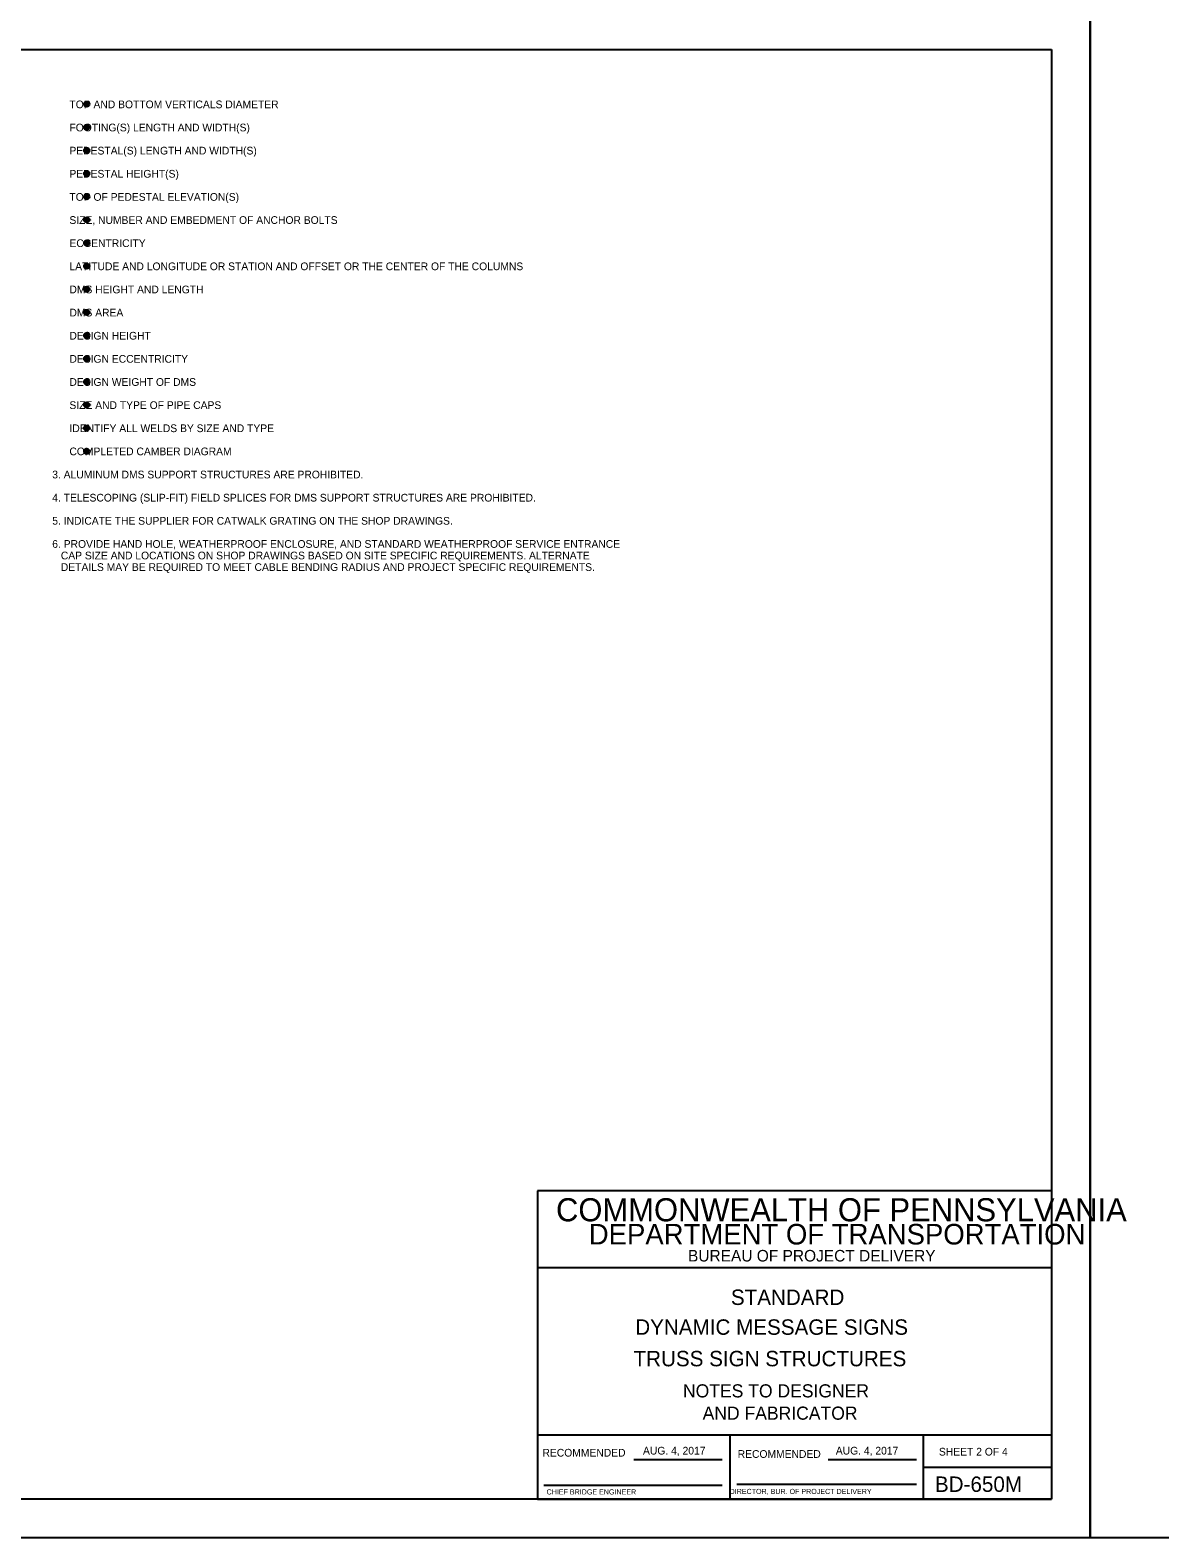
# Model space of a CAD drawing. Extents: x 3831399 to 3833095, y 499014 to 500202.
# Drawn here: x 3831828 to 3832267, y 499014 to 499601 of the extents above; entities that cross this region are included whole.
import ezdxf

# ---------------------------------------------------------------- set-up
doc = ezdxf.new("R2010")
doc.units = 0
for name, color, linetype in [('10', 7, 'Continuous'), ('2', 7, 'Continuous'), ('DIM TXT', 7, 'Continuous'), ('PLT-BNDY', 7, 'Continuous'), ('Pr_dimension_ln', 7, 'Continuous')]:
    doc.layers.add(name, color=color, linetype=linetype)

msp = doc.modelspace()

# ---------------------------------------------------------------- linework, layer by layer
at = {"layer": '2'}
for p, q in [((3831439.16, 499593.03), (3832225.16, 499593.03)), ((3832225.16, 499593.03), (3832225.16, 499029.03)), ((3832225.16, 499149.03), (3832025.16, 499149.03)), ((3832025.16, 499149.03), (3832025.16, 499029.03)), ((3832225.16, 499119.03), (3832025.16, 499119.03)), ((3832225.16, 499054.03), (3832025.16, 499054.03)), ((3832100.16, 499029.03), (3832100.16, 499054.03)), ((3832175.16, 499054.03), (3832175.16, 499029.03)), ((3832062.62, 499044.53), (3832097.03, 499044.53)), ((3832138.24, 499044.53), (3832172.65, 499044.53)), ((3832175.16, 499041.53), (3832225.16, 499041.53)), ((3832027.66, 499034.53), (3832097.03, 499034.53)), ((3832102.79, 499034.9), (3832172.65, 499034.9)), ((3832225.16, 499029.03), (3831439.16, 499029.03)), ((3832025.16, 499029.03), (3832225.16, 499029.03))]:
    msp.add_line(p, q, dxfattribs=at)
at = {"layer": 'DIM TXT'}
for centre, radius in [((3831849.87, 499571.73), 1.04), ((3831849.87, 499571.73), 0.783), ((3831849.87, 499571.73), 0.522), ((3831849.87, 499571.73), 0.261), ((3831849.87, 499571.73), 0.00000209), ((3831849.87, 499562.73), 1.04), ((3831849.87, 499562.73), 0.783), ((3831849.87, 499562.73), 0.522), ((3831849.87, 499562.73), 0.261), ((3831849.87, 499562.73), 0.00000209), ((3831849.87, 499553.73), 1.04), ((3831849.87, 499553.73), 0.783), ((3831849.87, 499553.73), 0.522), ((3831849.87, 499553.73), 0.261), ((3831849.87, 499553.73), 0.00000209), ((3831849.87, 499544.73), 1.04), ((3831849.87, 499544.73), 0.783), ((3831849.87, 499544.73), 0.522), ((3831849.87, 499544.73), 0.261), ((3831849.87, 499544.73), 0.00000209), ((3831849.87, 499535.73), 1.04), ((3831849.87, 499535.73), 0.783), ((3831849.87, 499535.73), 0.522), ((3831849.87, 499535.73), 0.261), ((3831849.87, 499535.73), 0.00000209), ((3831849.87, 499526.73), 1.04), ((3831849.87, 499526.73), 0.783), ((3831849.87, 499526.73), 0.522), ((3831849.87, 499526.73), 0.261), ((3831849.87, 499526.73), 0.00000209), ((3831849.87, 499517.73), 1.04), ((3831849.87, 499517.73), 0.783), ((3831849.87, 499517.73), 0.522), ((3831849.87, 499517.73), 0.261), ((3831849.87, 499517.73), 0.00000209), ((3831849.87, 499508.73), 1.04), ((3831849.87, 499508.73), 0.783), ((3831849.87, 499508.73), 0.522), ((3831849.87, 499508.73), 0.261), ((3831849.87, 499508.73), 0.00000209), ((3831849.87, 499499.73), 1.04), ((3831849.87, 499499.73), 0.783), ((3831849.87, 499499.73), 0.522), ((3831849.87, 499499.73), 0.261), ((3831849.87, 499499.73), 0.00000209), ((3831849.87, 499490.73), 1.04), ((3831849.87, 499490.73), 0.783), ((3831849.87, 499490.73), 0.522), ((3831849.87, 499490.73), 0.261), ((3831849.87, 499490.73), 0.00000209), ((3831849.87, 499481.73), 1.04), ((3831849.87, 499481.73), 0.783), ((3831849.87, 499481.73), 0.522), ((3831849.87, 499481.73), 0.261), ((3831849.87, 499481.73), 0.00000209), ((3831849.87, 499472.73), 1.04), ((3831849.87, 499472.73), 0.783), ((3831849.87, 499472.73), 0.522), ((3831849.87, 499472.73), 0.261), ((3831849.87, 499472.73), 0.00000209), ((3831849.87, 499463.73), 1.04), ((3831849.87, 499463.73), 0.783), ((3831849.87, 499463.73), 0.522), ((3831849.87, 499463.73), 0.261), ((3831849.87, 499463.73), 0.00000209), ((3831849.87, 499454.73), 1.04), ((3831849.87, 499454.73), 0.783), ((3831849.87, 499454.73), 0.522), ((3831849.87, 499454.73), 0.261), ((3831849.87, 499454.73), 0.00000209), ((3831849.87, 499445.73), 1.04), ((3831849.87, 499445.73), 0.783), ((3831849.87, 499445.73), 0.522), ((3831849.87, 499445.73), 0.261), ((3831849.87, 499445.73), 0.00000209), ((3831849.87, 499436.73), 1.04), ((3831849.87, 499436.73), 0.783), ((3831849.87, 499436.73), 0.522), ((3831849.87, 499436.73), 0.261), ((3831849.87, 499436.73), 0.00000209)]:
    msp.add_circle(centre, radius, dxfattribs=at)
at = {"layer": 'PLT-BNDY'}
for points in [[(3831399.16, 499608.03), (3832240.16, 499608.03), (3832240.16, 499014.03), (3831399.16, 499014.03)], [(3832240.16, 499608.03), (3833081.16, 499608.03), (3833081.16, 499014.03), (3832240.16, 499014.03)]]:
    msp.add_lwpolyline(points, close=True, dxfattribs=at)

# ---------------------------------------------------------------- texts
at = {"layer": '10'}
for s, height, p in [('STANDARD ', 6, (3832100.43, 499104.62)), ('DYNAMIC MESSAGE SIGNS', 6, (3832063.23, 499093.02)), ('TRUSS SIGN STRUCTURES', 6, (3832062.56, 499080.76)), ('NOTES TO DESIGNER', 5.1, (3832081.79, 499068.66)), ('AND FABRICATOR', 5.1, (3832089.44, 499059.99))]:
    msp.add_text(s, height=height, dxfattribs=at).set_placement(p)
at = {"layer": '2'}
for s, height, p in [('COMMONWEALTH OF PENNSYLVANIA', 9, (3832032.41, 499137.15)), ('DEPARTMENT OF TRANSPORTATION', 8.0002, (3832045.16, 499128.15)), ('BUREAU OF PROJECT DELIVERY', 4.5, (3832083.75, 499121.53)), ('AUG. 4, 2017', 3, (3832066.24, 499046.44)), ('AUG. 4, 2017', 3, (3832141.24, 499046.44)), ('SHEET 2 OF 4', 3, (3832181.36, 499046.04)), ('BD-650M', 6, (3832179.79, 499031.9)), ('CHIEF BRIDGE ENGINEER', 2.0002, (3832028.75, 499030.9)), ('   DIRECTOR, BUR. OF PROJECT DELIVERY', 2.0002, (3832097.63, 499031.08))]:
    msp.add_text(s, height=height, dxfattribs=at).set_placement(p)
for p in [(3832027.14, 499045.64), (3832103.07, 499045.15)]:
    msp.add_text('RECOMMENDED', height=3, rotation=360, dxfattribs=at).set_placement(p)
at = {"layer": 'Pr_dimension_ln'}
for s, p in [('       TOP AND BOTTOM VERTICALS DIAMETER', (3831835.34, 499570.15)), ('       FOOTING(S) LENGTH AND WIDTH(S)', (3831835.34, 499561.15)), ('       PEDESTAL(S) LENGTH AND WIDTH(S)', (3831835.34, 499552.16)), ('       PEDESTAL HEIGHT(S)', (3831835.34, 499543.16)), ('       TOP OF PEDESTAL ELEVATION(S)', (3831835.34, 499534.16)), ('       SIZE, NUMBER AND EMBEDMENT OF ANCHOR BOLTS', (3831835.34, 499525.16)), ('       ECCENTRICITY', (3831835.34, 499516.16)), ('       LATITUDE AND LONGITUDE OR STATION AND OFFSET OR THE CENTER OF THE COLUMNS', (3831835.34, 499507.16)), ('       DMS HEIGHT AND LENGTH', (3831835.34, 499498.16)), ('       DMS AREA', (3831835.34, 499489.16)), ('       DESIGN HEIGHT', (3831835.34, 499480.16)), ('       DESIGN ECCENTRICITY', (3831835.34, 499471.16)), ('       DESIGN WEIGHT OF DMS', (3831835.34, 499462.16)), ('       SIZE AND TYPE OF PIPE CAPS', (3831835.34, 499453.16)), ('       IDENTIFY ALL WELDS BY SIZE AND TYPE', (3831835.34, 499444.16)), ('       COMPLETED CAMBER DIAGRAM', (3831835.34, 499435.16)), (' 3. ALUMINUM DMS SUPPORT STRUCTURES ARE PROHIBITED.', (3831835.34, 499426.16)), (' 4. TELESCOPING (SLIP-FIT) FIELD SPLICES FOR DMS SUPPORT STRUCTURES ARE PROHIBITED.', (3831835.34, 499417.16)), (' 5. INDICATE THE SUPPLIER FOR CATWALK GRATING ON THE SHOP DRAWINGS.', (3831835.34, 499408.16)), (' 6. PROVIDE HAND HOLE, WEATHERPROOF ENCLOSURE, AND STANDARD WEATHERPROOF SERVICE ENTRANCE ', (3831835.34, 499399.16)), ('    CAP SIZE AND LOCATIONS ON SHOP DRAWINGS BASED ON SITE SPECIFIC REQUIREMENTS. ALTERNATE', (3831835.34, 499394.66)), ('    DETAILS MAY BE REQUIRED TO MEET CABLE BENDING RADIUS AND PROJECT SPECIFIC REQUIREMENTS.', (3831835.34, 499390.16))]:
    msp.add_text(s, height=2.9999, rotation=360, dxfattribs=at).set_placement(p)

doc.saveas('drawing.dxf')
